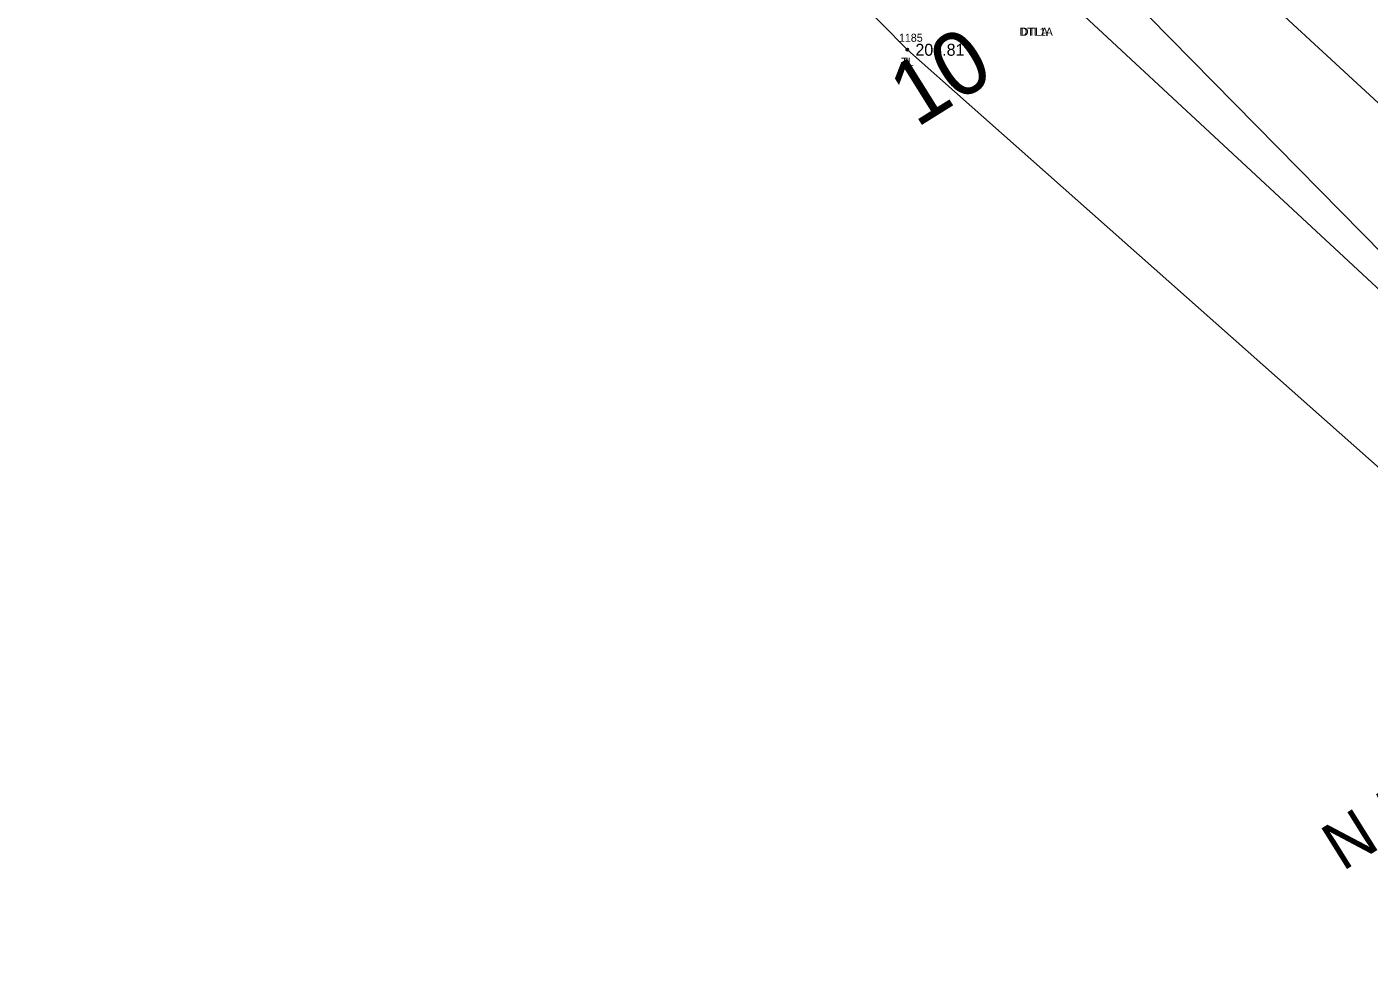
# Model space of a CAD drawing. Extents: x 2259948 to 2261336, y 1064647 to 1065986.
# Drawn here: x 2260257.3 to 2260425, y 1065302.5 to 1065419.1 of the extents above; entities that cross this region are included whole.
import ezdxf

# ---------------------------------------------------------------- set-up
doc = ezdxf.new("R2010")
doc.units = 0
for name, color, linetype in [('RD_EX_GuardRail', 7, 'Continuous'), ('RD_EX_H2O_txCode', 7, 'Continuous'), ('RD_EX_Road', 7, 'Continuous'), ('RD_EX_TX_VEG_ELEV', 7, 'Continuous'), ('RD_EX_VEG', 7, 'Continuous'), ('RD_EX_VEG_txCode', 7, 'Continuous'), ('RD_HC_Cl', 7, 'Continuous'), ('RD_HC_Data', 7, 'Continuous'), ('RD_HC_TX_Sta50', 7, 'Continuous'), ('RD_SMD_Locator', 7, 'Continuous')]:
    doc.layers.add(name, color=color, linetype=linetype)

msp = doc.modelspace()

# ---------------------------------------------------------------- linework, layer by layer
at = {"layer": 'RD_EX_GuardRail'}
msp.add_line((2260450.57, 1065363.73), (2260388.28, 1065421.56), dxfattribs=at)
at = {"layer": 'RD_EX_Road'}
msp.add_lwpolyline([(2260450.76, 1065366.34), (2260384.25, 1065433.92), (2260316.12, 1065498), (2260269.16, 1065540.98)], dxfattribs=at)
at = {"layer": 'RD_EX_VEG'}
msp.add_lwpolyline([(2261105.29, 1064796.67), (2260883, 1064984.96), (2260766.14, 1065062.68), (2260367.33, 1065416.28), (2260257.33, 1065527.76)], dxfattribs=at)
at = {"layer": 'RD_HC_Cl'}
msp.add_line((2260486.9, 1065353.51), (2260275.49, 1065548.81), dxfattribs=at)
at = {"layer": 'RD_SMD_Locator'}
msp.add_circle((2260367.33, 1065416.28), 0.15, dxfattribs=at)

# ---------------------------------------------------------------- texts
at = {"layer": 'RD_EX_H2O_txCode'}
for s, p in [('DTL1A', (2260381.34, 1065418.03)), ('DTLA', (2260381.5, 1065418.03))]:
    msp.add_text(s, height=1, dxfattribs=at).set_placement(p)
at = {"layer": 'RD_EX_TX_VEG_ELEV'}
msp.add_text('208.81', height=1.5, dxfattribs=at).set_placement((2260368.33, 1065415.53))
at = {"layer": 'RD_EX_VEG_txCode'}
for s, p in [('1185', (2260366.27, 1065417.28)), ('TL', (2260366.56, 1065414.28))]:
    msp.add_text(s, height=1, dxfattribs=at).set_placement(p)
at = {"layer": 'RD_HC_Data'}
msp.add_text('N 58%%d 00\' 02" E', height=6, rotation=31.9995, dxfattribs=at).set_placement((2260421.69, 1065313.55))
at = {"layer": 'RD_HC_TX_Sta50'}
msp.add_text('10', height=8, rotation=31.9995, dxfattribs=at).set_placement((2260368.45, 1065406.46))

doc.saveas('drawing.dxf')
